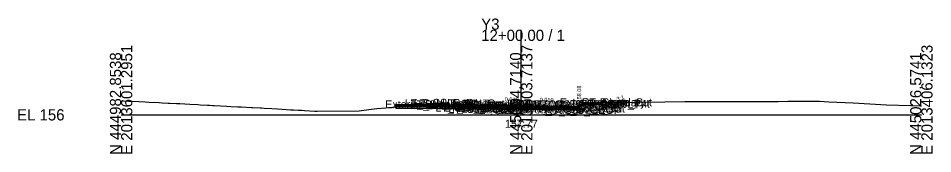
# Model space of a CAD drawing. Extents: x -26 to 203, y -10 to 5017.
# Drawn here: x -25.7 to 202.8, y 3990.3 to 4024.1 of the extents above; entities that cross this region are included whole.
import ezdxf

# ---------------------------------------------------------------- set-up
doc = ezdxf.new("R2010")
doc.units = 0
for name, color, linetype in [('Default', 7, 'Continuous'), ('Exist Cross Section Cell', 7, 'Continuous'), ('Exist XS Center Line Elevation Label', 7, 'Continuous'), ('Exist XS Ground Line', 7, 'Continuous'), ('Prop CMT Conc Surface', 7, 'Continuous'), ('Prop CMT Concrete Structures', 7, 'Continuous'), ('Prop CMT Pvmt Course 1', 7, 'Continuous'), ('Prop CMT Pvmt Course 1 CG', 7, 'Continuous'), ('Prop CMT Pvmt Course 2', 7, 'Continuous'), ('Prop CMT Pvmt Course 3', 7, 'Continuous'), ('Prop CMT Pvmt Surface', 7, 'Continuous'), ('Prop CMT Slope Grass', 7, 'Continuous'), ('Prop CMT Subgrade Earthwork', 7, 'Continuous'), ('Prop XS Earthwork Shape', 7, 'Continuous'), ('Prop XS Hydro Elevations', 7, 'Continuous'), ('Prop XS SE Text', 7, 'Continuous'), ('Prop XS Side Slope Text', 7, 'Continuous'), ('Scratch_Level_0', 7, 'Continuous')]:
    doc.layers.add(name, color=color, linetype=linetype)

msp = doc.modelspace()

# ---------------------------------------------------------------- linework, layer by layer
at = {"layer": 'Exist Cross Section Cell'}
for p, q in [((100, 4000), (100, 4021.24)), ((0, 4000), (100, 4000)), ((100, 4000), (200, 4000))]:
    msp.add_line(p, q, dxfattribs=at)
at = {"layer": 'Exist XS Ground Line'}
msp.add_lwpolyline([(0, 4003.52), (1.88, 4003.43), (2.73, 4003.38), (4.41, 4003.3), (6.02, 4003.22), (6.95, 4003.17), (9.5, 4003.06), (10.23, 4003.03), (11.73, 4002.95), (12.08, 4002.93), (13.84, 4002.84), (14.66, 4002.79), (15.94, 4002.72), (17.22, 4002.65), (19.22, 4002.56), (19.75, 4002.53), (21.61, 4002.43), (22.11, 4002.41), (22.83, 4002.36), (23.26, 4002.34), (24.88, 4002.25), (26.37, 4002.17), (27.46, 4002.11), (29.16, 4002.02), (30, 4001.97), (32.55, 4001.84), (32.93, 4001.82), (34.72, 4001.74), (35.13, 4001.71), (35.77, 4001.67), (37.69, 4001.57), (39.07, 4001.48), (40.25, 4001.41), (42.36, 4001.28), (43.09, 4001.24), (44.35, 4001.17), (45.16, 4001.13), (45.83, 4001.09), (48.45, 4000.92), (49.01, 4000.93), (59.47, 4001), (61.88, 4001.33), (63.89, 4001.55), (66.13, 4001.73), (66.84, 4001.8), (67.91, 4001.92), (68.86, 4001.99), (71.4, 4002.45), (73.56, 4002.8), (74.25, 4002.87), (76.14, 4003.01), (77.3, 4002.86), (78.94, 4002.92), (79.93, 4002.93), (80.42, 4002.97), (80.73, 4002.97), (81.79, 4002.64), (83.15, 4002.1), (83.86, 4002), (84.9, 4001.89), (85.97, 4001.61), (87.06, 4001.48), (87.57, 4001.4), (98.5, 4001.65), (100, 4001.77), (100.73, 4001.83), (102.58, 4001.71), (112.83, 4001.85), (113.63, 4001.97), (113.96, 4002), (117.16, 4002.85), (119.74, 4003.12), (129.49, 4003.13), (135.9, 4003.27), (140.93, 4003.29), (146.15, 4003.36), (154.13, 4003.3), (156.4, 4003.34), (164.23, 4003.37), (166.64, 4003.4), (174.57, 4003.42), (176.89, 4003.28), (182.95, 4003.01), (187.14, 4002.78), (191.32, 4002.48), (197.39, 4002.3), (199.69, 4002.24), (200, 4002.22)], dxfattribs=at)
at = {"layer": 'Prop CMT Conc Surface'}
for points in [[(112.48, 4002.18), (114.48, 4002.08)], [(114.48, 4002.08), (114.48, 4002.58), (114.98, 4002.58)]]:
    msp.add_lwpolyline(points, dxfattribs=at)
at = {"layer": 'Prop CMT Concrete Structures'}
for points in [[(112.48, 4002.18), (114.48, 4002.08), (114.48, 4002.58), (114.98, 4002.58)], [(114.98, 4002.58), (114.98, 4001.57), (112.48, 4001.6)], [(112.48, 4001.6), (112.48, 4002.18)]]:
    msp.add_lwpolyline(points, dxfattribs=at)
at = {"layer": 'Prop CMT Pvmt Course 1'}
for points in [[(100, 4002.31), (68.64, 4002.62)], [(68.64, 4002.62), (68.64, 4002.37)], [(68.64, 4002.37), (100, 4002.06)], [(100, 4002.06), (100, 4002.31)], [(100, 4002.31), (112.48, 4002.18)], [(100, 4002.06), (100, 4002.31)], [(112.48, 4001.93), (100, 4002.06)], [(112.48, 4002.18), (112.48, 4001.93)]]:
    msp.add_lwpolyline(points, dxfattribs=at)
msp.add_lwpolyline([(100, 4002.06), (100, 4002.18), (100, 4002.18), (100, 4002.06)], close=True, dxfattribs=at)
msp.add_lwpolyline([(100, 4002.06), (100, 4002.18), (100, 4002.18), (100, 4002.06)], close=True, dxfattribs=at)
at = {"layer": 'Prop CMT Pvmt Course 1 CG'}
for points in [[(68.64, 4001.7), (68.64, 4002.04)], [(112.48, 4001.6), (115.48, 4001.57), (115.81, 4001.23)], [(112.48, 4001.26), (112.48, 4001.6)], [(115.81, 4001.23), (112.48, 4001.26)]]:
    msp.add_lwpolyline(points, dxfattribs=at)
at = {"layer": 'Prop CMT Pvmt Course 2'}
for points in [[(100, 4002.06), (68.64, 4002.37)], [(68.64, 4002.37), (68.64, 4002.04)], [(68.64, 4002.04), (100, 4001.72)], [(100, 4001.72), (100, 4002.06)], [(100, 4001.72), (100, 4002.06)], [(100, 4002.06), (112.48, 4001.93)], [(112.48, 4001.6), (100, 4001.72)], [(112.48, 4001.93), (112.48, 4001.6)]]:
    msp.add_lwpolyline(points, dxfattribs=at)
at = {"layer": 'Prop CMT Pvmt Course 3'}
for points in [[(100, 4001.72), (68.64, 4002.04)], [(68.64, 4002.04), (68.64, 4001.7)], [(68.64, 4001.7), (100, 4001.39)], [(100, 4001.39), (100, 4001.72)], [(100, 4001.72), (112.48, 4001.6)], [(100, 4001.39), (100, 4001.72)], [(112.48, 4001.26), (100, 4001.39)], [(112.48, 4001.6), (112.48, 4001.26)]]:
    msp.add_lwpolyline(points, dxfattribs=at)
at = {"layer": 'Prop CMT Pvmt Surface'}
for points in [[(100, 4002.31), (68.64, 4002.62)], [(100, 4002.31), (112.48, 4002.18)]]:
    msp.add_lwpolyline(points, dxfattribs=at)
at = {"layer": 'Prop CMT Slope Grass'}
msp.add_lwpolyline([(114.98, 4002.58), (124.48, 4002.77), (125.54, 4003.13)], dxfattribs=at)
at = {"layer": 'Prop CMT Subgrade Earthwork'}
for p in [(68.64, 4002.62), (68.64, 4001.7)]:
    msp.add_line(p, (68.64, 4001.98), dxfattribs=at)
for points in [[(100, 4001.39), (68.64, 4001.7)], [(112.48, 4001.26), (115.81, 4001.23), (117.21, 4002.63)], [(100, 4001.39), (112.48, 4001.26)]]:
    msp.add_lwpolyline(points, dxfattribs=at)
at = {"layer": 'Prop XS Earthwork Shape'}
for points in [[(68.64, 4001.98), (68.86, 4001.99), (71.4, 4002.45), (72.23, 4002.58), (82.19, 4002.48), (83.15, 4002.1), (83.86, 4002), (84.9, 4001.89), (85.97, 4001.61), (86.7, 4001.52), (68.64, 4001.7)], [(76.14, 4003.01), (77.3, 4002.86), (78.94, 4002.92), (79.93, 4002.93), (80.42, 4002.97), (80.73, 4002.97), (81.79, 4002.64), (82.19, 4002.48), (72.23, 4002.58), (73.56, 4002.8), (74.25, 4002.87)], [(112.48, 4001.26), (115.81, 4001.23), (117.21, 4002.63), (116.24, 4002.61), (114.98, 4002.27), (114.98, 4001.57), (112.48, 4001.6), (112.48, 4001.85), (102.58, 4001.71), (100.73, 4001.83), (100, 4001.77), (98.5, 4001.65), (90.95, 4001.48), (100, 4001.39)], [(114.48, 4002.14), (114.98, 4002.27), (114.98, 4001.57), (112.48, 4001.6), (112.48, 4001.85), (112.83, 4001.85), (113.63, 4001.97), (113.96, 4002), (114.29, 4002.09), (114.48, 4002.08)], [(114.29, 4002.09), (114.48, 4002.14), (114.48, 4002.08)], [(124.48, 4002.77), (125.54, 4003.13), (119.74, 4003.12), (117.16, 4002.85), (116.24, 4002.61), (117.21, 4002.63)], [(86.7, 4001.52), (87.06, 4001.48), (87.57, 4001.4), (90.95, 4001.48)]]:
    msp.add_lwpolyline(points, close=True, dxfattribs=at)

# ---------------------------------------------------------------- texts
at = {"layer": 'Default'}
msp.add_text('-', height=0.0001, dxfattribs=at).set_placement((0, 4000))
at = {"layer": 'Exist Cross Section Cell'}
for s, p in [('Y3', (90, 4021.24)), ('12+00.00 / 1', (90, 4018.44)), ('EL 156', (-26, 3998.6))]:
    msp.add_text(s, height=2.8, dxfattribs=at).set_placement(p)
for s, p in [('N 444982.8538', (0, 3990)), ('E 2013601.2951', (2.8, 3990)), ('N 445004.7140', (100, 3990)), ('E 2013503.7137', (102.8, 3990)), ('N 445026.5741', (200, 3990)), ('E 2013406.1323', (202.8, 3990))]:
    msp.add_text(s, height=2.8, rotation=90, dxfattribs=at).set_placement(p)
at = {"layer": 'Exist XS Center Line Elevation Label'}
msp.add_text('157.77', height=2, dxfattribs=at).set_placement((95.94, 3996.77))
at = {"layer": 'Prop XS Hydro Elevations'}
msp.add_text('158.08', height=1, rotation=90, dxfattribs=at).set_placement((114.98, 4003.08))
at = {"layer": 'Prop XS SE Text'}
for p in [(95.88, 4003.35), (104.62, 4003.26)]:
    msp.add_text('0.010', height=1, rotation=359.4271, dxfattribs=at).set_placement(p)
at = {"layer": 'Prop XS Side Slope Text'}
msp.add_text('3:1', height=1, rotation=18.4332, dxfattribs=at).set_placement((124.02, 4003.41))
at = {"layer": 'Scratch_Level_0'}
for s, p in [('LT_Sub_Trench_Out_DLT', (70.87, 4001.84)), ('LT_CSLP_Pnt', (73.17, 4001.99)), ('Exterior Boundary', (109.68, 4002.13)), ('RT_Slope_Cut', (115.13, 4002.13)), ('Exterior Boundary', (66.01, 4001.61)), ('LT_Slope_Fill', (72.39, 4001.61)), ('LT_CG1_Shelf_Out', (78.55, 4000.8)), ('LT_CG_Top_Face', (80.26, 4001.8)), ('LT_CG_Top_BOC', (80.78, 4001.8)), ('LT_CG_Bot_BOC', (80.81, 4000.8)), ('LT_CG_Top_Gut', (81.24, 4001.3)), ('LT_Sub_OEOP', (81.78, 4000.47)), ('LT_CG_Bot_IE', (84.91, 4000.77)), ('LT_Sub_OEOT', (85.08, 4000.44)), ('LT_PV2_OEOT', (85.17, 4001.11)), ('LT_PV3_OEOT', (85.17, 4000.77)), ('LT_PV1_OEOT', (85.74, 4001.36)), ('RT_Sub_OEEOP', (89.17, 4000.39)), ('LT_Sub_OEEOP', (89.21, 4000.39)), ('RT_PV2_OEEOP', (89.26, 4001.06)), ('RT_PV3_OEEOP', (89.26, 4000.72)), ('LT_PV2_OEEOP', (89.31, 4001.06)), ('LT_PV3_OEEOP', (89.31, 4000.72)), ('RT_PV1_OEEOP', (89.83, 4001.18)), ('LT_PV1_OEEOP', (89.87, 4001.18)), ('RT_PV2_IEEOP', (89.91, 4001.06)), ('LT_PV2_IEEOP', (89.95, 4001.06)), ('RT_PV1_IEEOP', (90.47, 4001.18)), ('LT_PV1_IEEOP', (90.52, 4001.18)), ('PV2_PGL', (93.91, 4001.06)), ('PV1_PGL', (94.47, 4001.31)), ('RT_Sub_Trench_Out_DLT', (97.73, 4001.63)), ('RT_CG_Top_Face', (101.69, 4001.58)), ('RT_CG1_Shelf_Out', (101.98, 4000.57)), ('RT_CG_Bot_IE', (102.34, 4000.6)), ('RT_Sub_OEOT', (102.51, 4000.26)), ('RT_PV2_OEOT', (102.6, 4000.93)), ('RT_PV3_OEOT', (102.6, 4000.6)), ('RT_CG_Top_Gut', (102.67, 4001.08)), ('RT_PV1_OEOT', (103.17, 4001.18)), ('RT_CG_Top_BOC', (103.21, 4001.58)), ('RT_CG_Bot_BOC', (103.24, 4000.57)), ('RT_Sub_OEOP', (105.88, 4000.23)), ('RT_CSLP_Pnt', (114.6, 4001.77))]:
    msp.add_text(s, height=2, dxfattribs=at).set_placement(p)

doc.saveas('drawing.dxf')
